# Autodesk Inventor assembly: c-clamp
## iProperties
Shininess: 64.0
Length Units: 11272
Angle Units: 11279
Time Units: 11290
Mass Units: 11286
Length Display Precision: 3
Angle Display Precision: 2
Compacted: True
Part Number: c-clamp
Document SubType Name: Assembly
Created: 2002-11
Designer: E. MOSS
Density: 0.0
Volumn: 0.0
Area: 0.0
PropertySet Name: Model Information
Control State: 0
Master: False
Checked Out: False
Author: E. MOSS
